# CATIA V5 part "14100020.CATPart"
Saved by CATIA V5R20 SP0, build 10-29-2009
Part number: 14100020
Definition: NONE
Nomenclature: 14100020
Source: Unknown
Description: 14100020
Bounding box of the stored display mesh (mm): x -10 to 40, y -64 to 53.915, z -54.1 to 54.1
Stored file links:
  C:\Users\Utente\Desktop\IO LAVORO\3D X SITO CF\X SITO\PLASTICA\RF2\14100020.CATPart
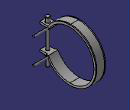
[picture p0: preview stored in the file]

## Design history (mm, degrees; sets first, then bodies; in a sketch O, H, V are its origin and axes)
Body1 "14100020" (main body)
  Solid1: solid without history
